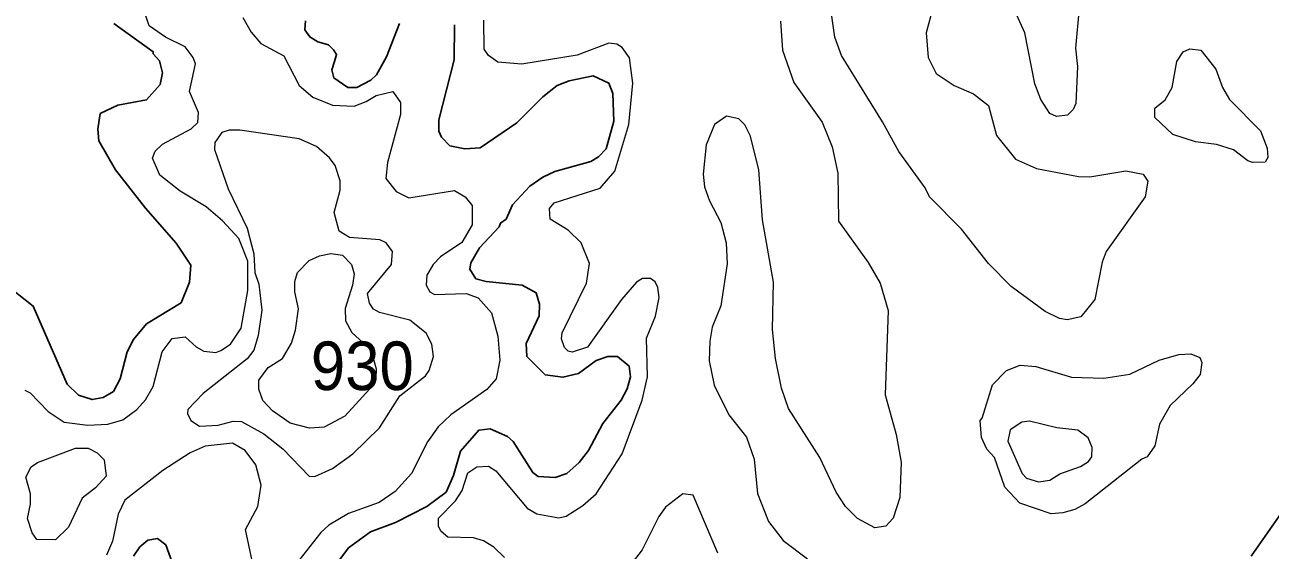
# Model space of a CAD drawing. Extents: x 763.2 to 816.8, y 7896.5 to 7952.7.
# Drawn here: x 774.699 to 778.802, y 7917.592 to 7919.324 of the extents above; entities that cross this region are included whole.
import ezdxf

# ---------------------------------------------------------------- set-up
doc = ezdxf.new("R2010")
doc.units = 0
doc.header["$LTSCALE"] = 0.064
doc.layers.add('1', color=7, linetype='Continuous', lineweight=25)
doc.layers.add('2', color=7, linetype='Continuous', lineweight=13)
doc.layers.add('21', color=7, linetype='Continuous')

msp = doc.modelspace()

# ---------------------------------------------------------------- linework, layer by layer
at = {"layer": '1'}
for points in [[(775.6229, 7919.3367), (775.6212, 7919.3071), (775.6376, 7919.284), (775.6639, 7919.2678), (775.6995, 7919.2579), (775.7159, 7919.2417), (775.7258, 7919.2264), (775.7186, 7919.203), (775.7096, 7919.176), (775.7168, 7919.149), (775.7456, 7919.1295), (775.7624, 7919.1177), (775.7922, 7919.1178), (775.8382, 7919.1416), (775.8575, 7919.1586), (775.8902, 7919.2189), (775.9333, 7919.3279)], [(774.6265, 7918.476), (774.7265, 7918.3969), (774.8383, 7918.1397), (774.8749, 7918.1031), (774.9206, 7918.0883), (774.9565, 7918.0949), (774.9906, 7918.1157), (775.0124, 7918.1565), (775.0358, 7918.2459), (775.0565, 7918.2868), (775.0997, 7918.3387), (775.2132, 7918.4078), (775.2412, 7918.4751), (775.246, 7918.5321), (775.1967, 7918.6041), (775.096, 7918.7198), (774.9974, 7918.8464), (774.9419, 7918.9413), (774.9389, 7918.9796), (774.9473, 7919.0312), (775.0046, 7919.0589), (775.0995, 7919.0772), (775.1442, 7919.1275), (775.1521, 7919.1662), (775.1426, 7919.2048), (775.1219, 7919.2281), (775.1219, 7919.2355), (774.9914, 7919.3284)], [(776.1138, 7919.3239), (776.1135, 7919.2082), (776.0629, 7919.0109), (776.063, 7918.9732), (776.071, 7918.9531), (776.0991, 7918.9249), (776.1484, 7918.9149), (776.1992, 7918.9183), (776.3195, 7919.0008), (776.4049, 7919.0861), (776.4523, 7919.1238), (776.4918, 7919.1399), (776.5717, 7919.1559), (776.623, 7919.1315), (776.6362, 7919.0972), (776.6396, 7919.0059), (776.6135, 7918.9155), (776.5892, 7918.889), (776.564, 7918.8738), (776.445, 7918.8404), (776.4057, 7918.8223), (776.3625, 7918.7926), (776.3051, 7918.7301), (776.2843, 7918.6831), (776.2657, 7918.6702), (776.2611, 7918.6581), (776.1965, 7918.5883), (776.1685, 7918.5391), (776.165, 7918.5189), (776.1846, 7918.487), (776.2182, 7918.4779), (776.3372, 7918.466), (776.383, 7918.441), (776.3946, 7918.4036), (776.3929, 7918.3643), (776.3506, 7918.2737), (776.3521, 7918.2308), (776.4132, 7918.1705), (776.4713, 7918.1621), (776.5227, 7918.1747), (776.5806, 7918.2177), (776.6199, 7918.231), (776.6515, 7918.2306), (776.6897, 7918.1988), (776.6937, 7918.1638), (776.6836, 7918.1238), (776.6634, 7918.0863), (776.6035, 7918.0092), (776.5562, 7917.9212), (776.5252, 7917.8815), (776.4841, 7917.8453), (776.4457, 7917.8319), (776.3904, 7917.8346), (776.3723, 7917.8478), (776.3071, 7917.9505), (776.2889, 7917.9668), (776.2317, 7917.9923), (776.1943, 7917.9875), (776.1336, 7917.9186), (776.1115, 7917.8381), (776.0868, 7917.7837), (776.0226, 7917.7362)], [(776.0226, 7917.7362), (775.9196, 7917.6836), (775.8377, 7917.6525), (775.7649, 7917.5994), (775.736, 7917.5619), (775.7277, 7917.5203)], [(778.7388, 7917.5728), (778.8395, 7917.715)], [(775.1833, 7917.5552), (775.1635, 7917.6094), (775.1357, 7917.6309), (775.1039, 7917.6254), (775.078, 7917.6028), (775.057, 7917.5729)]]:
    msp.add_lwpolyline(points, dxfattribs=at)
at = {"layer": '2'}
for points in [[(778.1844, 7919.5114), (778.1599, 7919.2466), (778.1665, 7919.1867), (778.1614, 7919.065), (778.1529, 7919.0451), (778.1343, 7919.0264), (778.0983, 7919.022), (778.0753, 7919.0312), (778.0462, 7919.0781), (778.0269, 7919.1291), (777.9937, 7919.2977), (777.9335, 7919.4311)], [(777.6839, 7919.3546), (777.6685, 7919.2977), (777.6752, 7919.2164), (777.7013, 7919.1636), (777.7606, 7919.1235), (777.8243, 7919.0963), (777.8734, 7919.0579), (777.9002, 7918.9592), (777.9622, 7918.8813), (778.0323, 7918.85), (778.1704, 7918.8241), (778.2075, 7918.8228), (778.3265, 7918.8424), (778.3832, 7918.8322), (778.3991, 7918.8085), (778.3903, 7918.7564), (778.2614, 7918.5772), (778.2478, 7918.5421), (778.2243, 7918.4182), (778.1783, 7918.3615), (778.1326, 7918.3511), (778.1074, 7918.3562), (778.0609, 7918.3791), (777.9489, 7918.4616), (777.8732, 7918.5373), (777.7846, 7918.6505), (777.6788, 7918.7572), (777.665, 7918.7865), (777.5781, 7918.9066), (777.5242, 7919.0045), (777.3889, 7919.2228), (777.3673, 7919.2835), (777.3506, 7919.3988)], [(775.35, 7918.6776), (775.2959, 7918.7237), (775.2108, 7918.7756), (775.1437, 7918.8282), (775.1195, 7918.884), (775.1279, 7918.908), (775.1518, 7918.9304), (775.2466, 7918.9809), (775.2681, 7919.0016), (775.2704, 7919.0353), (775.2411, 7919.1044), (775.2606, 7919.1957), (775.2535, 7919.2164), (775.2265, 7919.2511), (775.1615, 7919.2832), (775.1086, 7919.3205), (775.0949, 7919.3602)], [(775.4169, 7919.3477), (775.4442, 7919.2998), (775.4763, 7919.2619), (775.5515, 7919.2219), (775.6027, 7919.1236), (775.6472, 7919.0852), (775.7128, 7919.0596), (775.7838, 7919.0561), (775.8234, 7919.0707), (775.856, 7919.0912), (775.9113, 7919.1043), (775.9362, 7919.0678), (775.9362, 7919.0288), (775.8935, 7918.8697), (775.8878, 7918.8169), (775.9217, 7918.7746), (775.9635, 7918.754), (776.114, 7918.778), (776.1497, 7918.7568), (776.1728, 7918.7281), (776.1728, 7918.6642), (776.1388, 7918.6065), (776.0678, 7918.5596), (776.0435, 7918.5339), (776.0235, 7918.499), (776.0209, 7918.4662), (776.033, 7918.4439), (776.0488, 7918.435), (776.1525, 7918.4381), (776.1927, 7918.4245), (776.2365, 7918.3748), (776.2568, 7918.2971), (776.2632, 7918.2182), (776.2516, 7918.1574), (776.2205, 7918.1213), (776.1018, 7918.038), (776.0602, 7917.9983), (776.0248, 7917.9494), (775.9723, 7917.8448), (775.9193, 7917.7851), (775.8666, 7917.7493), (775.7648, 7917.7129), (775.7002, 7917.6743), (775.6734, 7917.6509), (775.6011, 7917.558)], [(776.7891, 7918.4253), (776.7845, 7918.4582), (776.7754, 7918.4763), (776.7605, 7918.4873), (776.734, 7918.4873), (776.7135, 7918.4754), (776.6648, 7918.419), (776.5528, 7918.2616), (776.5022, 7918.2445), (776.4887, 7918.2477), (776.4766, 7918.2598), (776.4672, 7918.2886), (776.4689, 7918.3083), (776.549, 7918.4721), (776.5593, 7918.537), (776.5318, 7918.6051), (776.4884, 7918.6467), (776.4297, 7918.6833), (776.4277, 7918.7182), (776.4426, 7918.737), (776.5939, 7918.7853), (776.6425, 7918.8419), (776.6889, 7918.9953), (776.702, 7919.1314), (776.6904, 7919.2154), (776.6665, 7919.249), (776.6495, 7919.2597), (776.6223, 7919.2632), (776.518, 7919.2238), (776.3366, 7919.1942), (776.2574, 7919.201), (776.2266, 7919.2228), (776.2123, 7919.244), (776.2109, 7919.3391)], [(777.1885, 7919.3355), (777.1955, 7919.2404), (777.2327, 7919.1335), (777.3258, 7919.0031), (777.3591, 7918.9218), (777.3777, 7918.835), (777.3794, 7918.6771), (777.477, 7918.5404), (777.5171, 7918.4727), (777.5431, 7918.3821), (777.5338, 7918.1046), (777.5697, 7917.9731), (777.5859, 7917.8825), (777.5811, 7917.7654), (777.56, 7917.6978), (777.5351, 7917.6708), (777.4997, 7917.6661), (777.4419, 7917.697), (777.4028, 7917.7359), (777.3723, 7917.7831), (777.3179, 7917.8981), (777.2146, 7918.0592), (777.1912, 7918.1265), (777.172, 7918.2244)], [(777.0897, 7918.9565), (777.071, 7918.994), (777.051, 7919.0141), (777.011, 7919.023), (776.971, 7918.9958), (776.9435, 7918.9281), (776.934, 7918.8316), (776.9385, 7918.7897), (776.9546, 7918.7436), (776.9915, 7918.6726), (777.0091, 7918.6056), (777.0127, 7918.5358), (776.9915, 7918.3978), (776.9634, 7918.3273), (776.9553, 7918.2813), (776.9536, 7918.2163), (776.9695, 7918.1357), (777.0181, 7918.0383), (777.0759, 7917.9645), (777.1018, 7917.8917), (777.1131, 7917.7785), (777.1492, 7917.6872), (777.1973, 7917.6241), (777.2773, 7917.5632)], [(777.172, 7918.2244), (777.1623, 7918.3201), (777.1654, 7918.4758), (777.1296, 7918.6815), (777.1175, 7918.8456), (777.0897, 7918.9565)], [(775.3764, 7918.2709), (775.4118, 7918.3244), (775.4331, 7918.4482), (775.4331, 7918.5449), (775.4035, 7918.62), (775.35, 7918.6776)], [(776.6668, 7917.9094), (776.7328, 7918.0868), (776.7497, 7918.1637), (776.7464, 7918.2912), (776.7767, 7918.3631), (776.7891, 7918.4253)], [(774.6986, 7918.1193), (774.7165, 7918.1108), (774.7749, 7918.0498), (774.828, 7918.0145), (774.9061, 7918.0043), (774.9717, 7918.0073), (775.0212, 7918.0221), (775.0673, 7918.0557), (775.096, 7918.0876), (775.1211, 7918.1316), (775.1512, 7918.2465), (775.184, 7918.29), (775.2273, 7918.2958), (775.2631, 7918.262), (775.288, 7918.248), (775.3275, 7918.2443), (775.3445, 7918.2504), (775.3764, 7918.2709)], [(775.4474, 7917.5567), (775.426, 7917.6606), (775.4658, 7917.7358), (775.4776, 7917.806), (775.4599, 7917.8738), (775.4245, 7917.9209), (775.3824, 7917.9449), (775.2923, 7917.9351), (775.2437, 7917.9125), (775.1535, 7917.8543), (775.028, 7917.7566), (775.0063, 7917.7108), (774.9874, 7917.6218), (774.9671, 7917.5757)], [(776.2788, 7917.5676), (776.2436, 7917.6016), (776.2093, 7917.6229), (776.1769, 7917.6326), (776.0924, 7917.6348), (776.0705, 7917.6533), (776.0616, 7917.6702), (776.0616, 7917.6972), (776.1177, 7917.7552), (776.1396, 7917.7885), (776.1578, 7917.8469), (776.1874, 7917.8665), (776.2261, 7917.8695), (776.2506, 7917.854), (776.3542, 7917.7309), (776.385, 7917.7121), (776.4576, 7917.6988), (776.482, 7917.7045), (776.5372, 7917.7394), (776.5809, 7917.7781), (776.6668, 7917.9094)], [(776.9819, 7917.582), (776.9009, 7917.7735), (776.8662, 7917.7776), (776.81, 7917.7342), (776.7876, 7917.7032), (776.7323, 7917.5932), (776.6923, 7917.5408)]]:
    msp.add_lwpolyline(points, dxfattribs=at)
for points in [[(778.494, 7919.2031), (778.515, 7919.235), (778.5372, 7919.2449), (778.5737, 7919.2406), (778.6223, 7919.178), (778.6445, 7919.1176), (778.6677, 7919.0775), (778.7702, 7918.9743), (778.7923, 7918.9171), (778.7942, 7918.8864), (778.7858, 7918.871), (778.7435, 7918.8705), (778.7282, 7918.8758), (778.681, 7918.9118), (778.6249, 7918.9294), (778.5553, 7918.938), (778.4814, 7918.9622), (778.4217, 7919.0184), (778.4216, 7919.0492), (778.456, 7919.0765), (778.4792, 7919.1178)], [(776.0191, 7918.1668), (776.0312, 7918.184), (776.0448, 7918.2305), (776.0401, 7918.2709), (776.0207, 7918.3077), (775.9672, 7918.3502), (775.8673, 7918.3758), (775.8471, 7918.3863), (775.8342, 7918.4059), (775.8281, 7918.4381), (775.9067, 7918.5343), (775.9098, 7918.5772), (775.889, 7918.6051), (775.8685, 7918.615), (775.7687, 7918.6224), (775.7344, 7918.6443), (775.7179, 7918.7058), (775.7373, 7918.7784), (775.7376, 7918.8099), (775.7208, 7918.8605), (775.7025, 7918.8853), (775.6595, 7918.9232), (775.6022, 7918.9481), (775.4065, 7918.9772), (775.3721, 7918.9768), (775.3476, 7918.9685), (775.3251, 7918.9361), (775.3235, 7918.9126), (775.3684, 7918.7837), (775.4316, 7918.6533), (775.4531, 7918.5688), (775.4564, 7918.508), (775.4693, 7918.4694), (775.4791, 7918.3832), (775.4673, 7918.2995), (775.4526, 7918.2512), (775.431, 7918.2224), (775.2867, 7918.109), (775.2351, 7918.0557), (775.2345, 7918.0432), (775.246, 7918.0192), (775.2737, 7918.0011), (775.3358, 7918.004), (775.3852, 7918.017), (775.4129, 7918.0168), (775.4865, 7917.9759), (775.549, 7917.9264), (775.6357, 7917.8364), (775.654, 7917.8354), (775.7121, 7917.8611), (775.779, 7917.9095), (775.8668, 7917.9956), (775.934, 7918.1007)], [(775.5148, 7918.0517), (775.4824, 7918.0855), (775.4699, 7918.1228), (775.4696, 7918.1526), (775.5003, 7918.1945), (775.5471, 7918.2238), (775.5771, 7918.2743), (775.5905, 7918.317), (775.6, 7918.3874), (775.5879, 7918.4438), (775.5881, 7918.4773), (775.5972, 7918.5075), (775.6355, 7918.5469), (775.6699, 7918.5628), (775.7073, 7918.5697), (775.7454, 7918.5645), (775.7747, 7918.5337), (775.7833, 7918.5029), (775.7784, 7918.4662), (775.7542, 7918.3886), (775.7556, 7918.3479), (775.7757, 7918.3096), (775.8387, 7918.253), (775.8557, 7918.19), (775.8556, 7918.1588), (775.8467, 7918.1362), (775.7528, 7918.0343), (775.6851, 7917.9975), (775.6365, 7917.9946), (775.5728, 7918.0104)], [(778.2539, 7918.1588), (778.339, 7918.172), (778.4366, 7918.218), (778.5007, 7918.2377), (778.5401, 7918.2393), (778.57, 7918.2272), (778.577, 7918.2113), (778.5708, 7918.1708), (778.5471, 7918.1402), (778.4719, 7918.0688), (778.4369, 7918.008), (778.4218, 7917.9363), (778.3965, 7917.8998), (778.3785, 7917.8924), (778.1927, 7917.7447), (778.1582, 7917.7266), (778.1181, 7917.7149), (778.08, 7917.7118), (777.9772, 7917.7468), (777.9279, 7917.7994), (777.8934, 7917.8975), (777.8683, 7917.9252), (777.851, 7917.9633), (777.8461, 7918.0201), (777.8529, 7918.0271), (777.8867, 7918.1367), (777.9327, 7918.1846), (777.9781, 7918.2015), (778.03, 7918.1981), (778.1469, 7918.1624)], [(778.2017, 7917.963), (778.1681, 7917.9876), (778.0992, 7917.995), (778.0091, 7918.0173), (777.9835, 7918.0137), (777.9454, 7917.9885), (777.9379, 7917.9511), (777.9844, 7917.8445), (777.9989, 7917.8299), (778.038, 7917.8171), (778.0755, 7917.8234), (778.1085, 7917.8438), (778.1774, 7917.8678), (778.2033, 7917.8841), (778.214, 7917.9001), (778.2158, 7917.9311)], [(774.7232, 7917.6497), (774.7071, 7917.697), (774.7168, 7917.7438), (774.7168, 7917.7778), (774.7024, 7917.8333), (774.7191, 7917.8666), (774.74, 7917.8808), (774.8655, 7917.9282), (774.9067, 7917.9286), (774.9366, 7917.9135), (774.9599, 7917.8901), (774.9665, 7917.8358), (774.9313, 7917.798), (774.8876, 7917.7639), (774.8422, 7917.6678), (774.7999, 7917.6258), (774.7378, 7917.6278)]]:
    msp.add_lwpolyline(points, close=True, dxfattribs=at)

# ---------------------------------------------------------------- texts
at = {"layer": '21', "width": 0.95}
msp.add_text('930', height=0.16, dxfattribs=at).set_placement((775.641, 7918.12))

doc.saveas('drawing.dxf')
